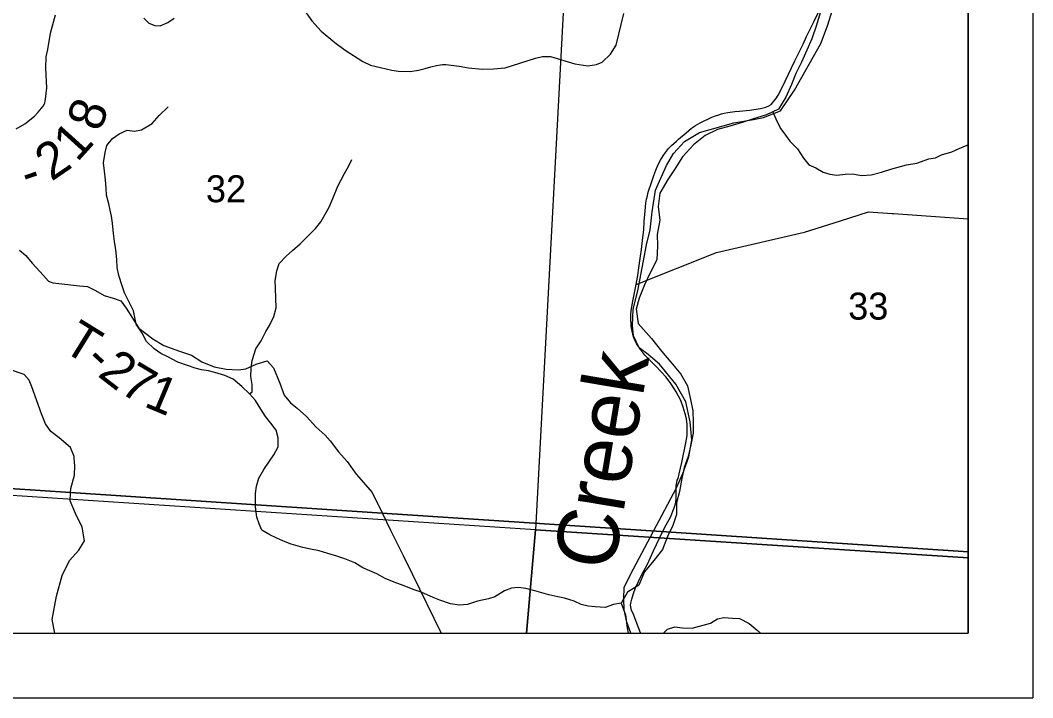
# Model space of a CAD drawing. Extents: x 0 to 34, y 0 to 22.
# Drawn here: x 7.429 to 9, y 14 to 15.051 of the extents above; entities that cross this region are included whole.
import ezdxf

# ---------------------------------------------------------------- set-up
doc = ezdxf.new("R2010")
doc.units = 0
for name, color, linetype in [('GM_X_County_Road', 7, 'Continuous'), ('GM_X_Minor_River', 7, 'Continuous'), ('GM_X_Minor_River_Text', 7, 'Continuous'), ('GM_X_Rail_Line', 7, 'Continuous'), ('GM_X_Section', 7, 'Continuous'), ('GM_X_Section_Text', 7, 'Continuous'), ('GM_X_Township_Road', 7, 'Continuous'), ('GM_X_Township_Road_Text', 7, 'Continuous'), ('GM_X_Unincorporated', 7, 'Continuous'), ('SH_Cut_Line', 7, 'Continuous'), ('SH_Data', 7, 'Continuous')]:
    doc.layers.add(name, color=color, linetype=linetype)

msp = doc.modelspace()

# ---------------------------------------------------------------- linework, layer by layer
at = {"layer": 'GM_X_County_Road'}
for points in [[(7.5131, 14.3715), (7.5129, 14.3744), (7.5073, 14.3881), (7.4899, 14.403), (7.4767, 14.4133), (7.4684, 14.4248), (7.4625, 14.4404), (7.4476, 14.4826), (7.4431, 14.4929), (7.4356, 14.5013), (7.4129, 14.5094)], [(7.4832, 14.1), (7.479, 14.1216), (7.4857, 14.1577), (7.4946, 14.1899), (7.5058, 14.213), (7.5206, 14.2292), (7.5291, 14.2432), (7.5254, 14.2645), (7.515, 14.2859), (7.5067, 14.3053), (7.5075, 14.3177), (7.508, 14.3246), (7.5138, 14.3451), (7.5139, 14.3599), (7.5135, 14.3657), (7.5131, 14.3715)]]:
    msp.add_lwpolyline(points, dxfattribs=at)
at = {"layer": 'GM_X_Minor_River'}
for points in [[(8.6705, 15.0627), (8.6644, 15.0437), (8.6571, 15.0221), (8.6495, 15.0049), (8.6412, 14.9859), (8.6324, 14.9688), (8.6256, 14.9513), (8.6168, 14.9316), (8.6058, 14.913), (8.5872, 14.9046), (8.5668, 14.8982), (8.5493, 14.8925), (8.53, 14.8868), (8.5111, 14.8819), (8.4917, 14.8724), (8.4739, 14.8579), (8.4568, 14.8393), (8.4451, 14.8214), (8.434, 14.8043), (8.4215, 14.7827), (8.4192, 14.7621), (8.4218, 14.7412), (8.4176, 14.7188), (8.4179, 14.7013), (8.4171, 14.6796), (8.4065, 14.6595), (8.3977, 14.6408), (8.3893, 14.6199), (8.3851, 14.6028), (8.3881, 14.5804), (8.4085, 14.5572), (8.424, 14.5378), (8.4387, 14.5206), (8.4542, 14.502), (8.4647, 14.4841), (8.4692, 14.4628), (8.4726, 14.4449), (8.4733, 14.4278), (8.4733, 14.4107), (8.4698, 14.3924), (8.4656, 14.3742), (8.4591, 14.3571), (8.4553, 14.3377), (8.4519, 14.3198), (8.4476, 14.3023), (8.4476, 14.2845), (8.4415, 14.267), (8.4335, 14.2499), (8.4259, 14.2301), (8.4122, 14.213), (8.3978, 14.1955), (8.3891, 14.1746), (8.3716, 14.1636), (8.3614, 14.1465), (8.3685, 14.1286), (8.3711, 14.1084), (8.3724, 14.1)], [(7.6068, 14.879), (7.6174, 14.8813), (7.6341, 14.8908), (7.645, 14.9033), (7.659, 14.9166)], [(8.5969, 14.9089), (8.6031, 14.8948), (8.6091, 14.8827), (8.6166, 14.8728), (8.6234, 14.8633), (8.6351, 14.8515), (8.6445, 14.837), (8.6525, 14.8267), (8.6634, 14.8222), (8.6748, 14.8157), (8.6853, 14.8122), (8.6959, 14.811), (8.7088, 14.8121), (8.7205, 14.8129), (8.7345, 14.8101), (8.7493, 14.8112), (8.7652, 14.8157), (8.78, 14.8202), (8.8042, 14.827), (8.8201, 14.8296), (8.8387, 14.8359), (8.8489, 14.8378), (8.8584, 14.8423), (8.8743, 14.8472), (8.886, 14.8521), (8.8985, 14.8574), (8.9, 14.8578)], [(8.3614, 14.1465), (8.3499, 14.1444), (8.3366, 14.1399), (8.3215, 14.141), (8.3105, 14.1421), (8.2996, 14.1448), (8.2886, 14.1497), (8.2735, 14.1546), (8.2633, 14.1565), (8.2493, 14.1599), (8.2387, 14.163), (8.2278, 14.166), (8.2138, 14.1694), (8.2017, 14.1709), (8.1915, 14.1701), (8.1805, 14.166), (8.1658, 14.1568), (8.1559, 14.1534), (8.1389, 14.1496), (8.1231, 14.1447), (8.1106, 14.1435), (8.0966, 14.1458), (8.0803, 14.1515), (8.0698, 14.1553), (8.0512, 14.164), (8.0388, 14.1681), (8.0248, 14.1734), (8.0093, 14.1795), (7.9957, 14.1848), (7.9824, 14.1924), (7.9609, 14.2018), (7.9484, 14.2094), (7.9329, 14.2155), (7.9205, 14.2196), (7.9065, 14.2238), (7.8932, 14.228), (7.8796, 14.2306), (7.8679, 14.2329), (7.8498, 14.2382), (7.8377, 14.2427), (7.8275, 14.2477), (7.8165, 14.2526), (7.8044, 14.2598), (7.7999, 14.2696), (7.7965, 14.2799), (7.7946, 14.2962), (7.7942, 14.3057), (7.7946, 14.317), (7.7961, 14.3284), (7.7995, 14.3406), (7.8071, 14.3542), (7.8162, 14.3671), (7.8226, 14.377), (7.8294, 14.3895), (7.8294, 14.4032), (7.8264, 14.4149), (7.8184, 14.4259), (7.8101, 14.4362), (7.8029, 14.4479), (7.7943, 14.4612), (7.7852, 14.4714), (7.7731, 14.4828), (7.7595, 14.4942), (7.747, 14.4998), (7.7315, 14.5044), (7.7213, 14.507), (7.7107, 14.5085), (7.7009, 14.5112), (7.6888, 14.5157), (7.6737, 14.5207), (7.6574, 14.5294), (7.6476, 14.5343), (7.637, 14.5415), (7.6253, 14.5529), (7.6185, 14.5654), (7.6094, 14.5794), (7.6053, 14.6003), (7.5977, 14.6147), (7.5913, 14.6283), (7.5875, 14.6389), (7.5826, 14.6553), (7.58, 14.6674), (7.5792, 14.6799), (7.5777, 14.6947), (7.5758, 14.708), (7.5743, 14.7205), (7.5724, 14.7364), (7.5709, 14.747), (7.569, 14.7565), (7.5671, 14.7664), (7.5634, 14.7796), (7.5626, 14.7903), (7.5618, 14.8035), (7.56, 14.8168), (7.5584, 14.8297), (7.5611, 14.846), (7.5637, 14.8566), (7.5728, 14.8676), (7.583, 14.8749), (7.5951, 14.8806), (7.6068, 14.879)], [(7.7852, 14.4714), (7.789, 14.4748), (7.789, 14.4858), (7.7871, 14.4984), (7.7875, 14.5116), (7.7894, 14.5234), (7.795, 14.5412), (7.803, 14.5537), (7.8102, 14.5682), (7.8162, 14.5776), (7.8226, 14.5913), (7.8264, 14.605), (7.826, 14.6201), (7.8253, 14.6357), (7.8249, 14.6474), (7.8276, 14.6626), (7.831, 14.6736), (7.8419, 14.685), (7.8518, 14.6941), (7.8639, 14.704), (7.8877, 14.7279), (7.8956, 14.7385), (7.902, 14.7495), (7.9085, 14.7613), (7.9141, 14.7746), (7.9221, 14.7935), (7.9274, 14.8034), (7.9323, 14.8133), (7.9387, 14.8243), (7.944, 14.8349)], [(8.427, 14.1), (8.4334, 14.1066), (8.4447, 14.11), (8.4565, 14.1085), (8.4716, 14.1081), (8.4833, 14.1108), (8.4999, 14.1157), (8.5109, 14.1222), (8.5207, 14.1245), (8.5343, 14.1237), (8.5453, 14.123), (8.56, 14.1154), (8.5725, 14.1048), (8.5779, 14.1)]]:
    msp.add_lwpolyline(points, dxfattribs=at)
at = {"layer": 'GM_X_Rail_Line'}
msp.add_lwpolyline([(8.3764, 14.1), (8.3704, 14.117), (8.3663, 14.1363), (8.3655, 14.1532), (8.3663, 14.171), (8.376, 14.1911), (8.4476, 14.3255), (8.4572, 14.348), (8.4665, 14.374), (8.471, 14.3998), (8.4685, 14.4281), (8.4619, 14.4593), (8.4466, 14.4864), (8.4208, 14.5178), (8.4108, 14.5265), (8.4033, 14.5326), (8.3897, 14.5428), (8.3808, 14.5613), (8.3793, 14.5778), (8.38, 14.6031), (8.3873, 14.6313), (8.4009, 14.7029), (8.4066, 14.7259), (8.4097, 14.7537), (8.4146, 14.7874), (8.4318, 14.8256), (8.4428, 14.8446), (8.4599, 14.8628), (8.4831, 14.877), (8.5363, 14.8921), (8.5668, 14.8972), (8.5825, 14.9002), (8.6085, 14.9106), (8.6302, 14.9428), (8.6712, 15.0152), (8.6817, 15.0426), (8.6979, 15.0941)], dxfattribs=at)
at = {"layer": 'GM_X_Section'}
msp.add_lwpolyline([(8.2829, 15.2756), (8.2289, 14.2604), (7.2187, 14.3265), (7.27, 15.3432)], close=True, dxfattribs=at)
at = {"layer": 'GM_X_Township_Road'}
for p, q in [((8.784, 14.7511), (8.9, 14.7429)), ((8.0372, 14.1923), (8.0826, 14.1))]:
    msp.add_line(p, q, dxfattribs=at)
for points in [[(7.8619, 15.0779), (7.882, 15.0501), (7.8962, 15.0344), (7.9174, 15.0169), (7.9337, 15.005), (7.9609, 14.987), (7.9727, 14.9813), (7.9882, 14.9776), (8.0059, 14.9736), (8.0163, 14.9723), (8.0344, 14.9719), (8.047, 14.9735), (8.0574, 14.9764), (8.0664, 14.9791), (8.0749, 14.9808), (8.0844, 14.9824), (8.0898, 14.9826), (8.1103, 14.9798), (8.125, 14.9772), (8.1459, 14.9753), (8.1635, 14.976), (8.1819, 14.9775), (8.2289, 14.9924), (8.2398, 14.9951), (8.252, 14.9949), (8.2897, 14.9835), (8.3098, 14.9805), (8.3231, 14.9827), (8.3321, 14.9859), (8.3448, 14.9984), (8.354, 15.0125), (8.3656, 15.0614)], [(8.4119, 14.2277), (8.4257, 14.2572), (8.4316, 14.2684), (8.4379, 14.2803), (8.444, 14.2945), (8.4456, 14.2995), (8.4464, 14.3031), (8.4468, 14.3084), (8.4468, 14.3171), (8.4468, 14.325), (8.4471, 14.3293), (8.4481, 14.3337), (8.4487, 14.3378), (8.4498, 14.3402), (8.4516, 14.3476), (8.4559, 14.3652), (8.4618, 14.3957), (8.4638, 14.4068), (8.464, 14.4153), (8.4638, 14.4241), (8.4628, 14.4328), (8.461, 14.4403), (8.4578, 14.4509), (8.454, 14.4612), (8.4471, 14.4745), (8.4445, 14.4787), (8.4384, 14.4878), (8.4315, 14.4972), (8.4237, 14.5055), (8.4149, 14.5149), (8.4074, 14.522), (8.4028, 14.5271), (8.3985, 14.5315), (8.3952, 14.5355), (8.3913, 14.5402), (8.3884, 14.5448), (8.3854, 14.5496), (8.3824, 14.5558), (8.3802, 14.5614), (8.3779, 14.5711), (8.3772, 14.5764), (8.3769, 14.5817), (8.3766, 14.5854), (8.3766, 14.5892), (8.3767, 14.5939), (8.3771, 14.6006), (8.3779, 14.6065), (8.3798, 14.6155), (8.3847, 14.641), (8.3872, 14.6552), (8.3886, 14.6634), (8.3916, 14.6849), (8.3931, 14.6956), (8.3953, 14.7141), (8.3965, 14.7258), (8.3975, 14.7391), (8.3986, 14.7553), (8.4, 14.7676), (8.401, 14.7737), (8.4022, 14.7787), (8.4031, 14.7824), (8.4041, 14.786), (8.4084, 14.7994), (8.4122, 14.8101), (8.4153, 14.8184), (8.419, 14.8274), (8.4228, 14.834), (8.4266, 14.8406), (8.4303, 14.8458), (8.4352, 14.852), (8.4397, 14.8569), (8.4472, 14.8638), (8.4505, 14.8664), (8.4623, 14.8766), (8.4705, 14.8835), (8.477, 14.888), (8.4842, 14.8922), (8.502, 14.9008), (8.508, 14.903), (8.513, 14.9046), (8.5173, 14.9059), (8.5213, 14.907), (8.5271, 14.9082), (8.5343, 14.9092), (8.5381, 14.9096), (8.5452, 14.9102), (8.5609, 14.9117), (8.5778, 14.914), (8.5858, 14.9161), (8.5904, 14.9184), (8.5942, 14.9207), (8.5982, 14.9254), (8.6015, 14.9293), (8.605, 14.9348), (8.6098, 14.9438), (8.6158, 14.9568), (8.631, 14.988), (8.6438, 15.0142), (8.6493, 15.0257), (8.661, 15.05), (8.6683, 15.0648)], [(7.4232, 14.8827), (7.4367, 14.8905), (7.4518, 14.9025), (7.4575, 14.9084), (7.4649, 14.9176), (7.4676, 14.9227), (7.4689, 14.9286), (7.4705, 14.9465), (7.4693, 14.9766), (7.4699, 14.9944), (7.4722, 15.0058), (7.4765, 15.031), (7.4842, 15.0595)], [(7.621, 15.0544), (7.6289, 15.0465), (7.6381, 15.0432), (7.6465, 15.0427), (7.6584, 15.0478), (7.6682, 15.0544)], [(8.3847, 14.641), (8.5094, 14.6907), (8.6461, 14.7223), (8.702, 14.7401), (8.745, 14.7539), (8.7821, 14.7512), (8.784, 14.7511)], [(7.4285, 14.6943), (7.4379, 14.6862), (7.4478, 14.6745), (7.4655, 14.655), (7.4733, 14.6465), (7.48, 14.6438), (7.4984, 14.6416), (7.5214, 14.6393), (7.5337, 14.6378), (7.5464, 14.6317), (7.5594, 14.624), (7.5736, 14.6198), (7.5855, 14.6156), (7.5939, 14.6044), (7.6132, 14.5735), (7.635, 14.5571), (7.652, 14.5463), (7.6763, 14.5378), (7.6952, 14.5313), (7.7114, 14.5213), (7.7303, 14.5136), (7.7489, 14.51), (7.7682, 14.5088), (7.7796, 14.5102), (7.7956, 14.5177), (7.8123, 14.5226), (7.8221, 14.5119), (7.8322, 14.4879), (7.8389, 14.4692), (7.8487, 14.4574), (7.8592, 14.4494), (7.8736, 14.4364), (7.8883, 14.4199), (7.9022, 14.4073), (7.9101, 14.3985), (7.9233, 14.3814), (7.9365, 14.3665), (7.9507, 14.347), (7.9513, 14.3463), (7.9752, 14.3184), (7.9912, 14.2858), (8.0038, 14.2602), (8.0233, 14.2207), (8.0372, 14.1923)], [(8.3917, 14.1), (8.3915, 14.1005), (8.3864, 14.1143), (8.381, 14.1279), (8.3777, 14.1358), (8.3766, 14.1409), (8.3763, 14.1437), (8.3768, 14.1468), (8.3779, 14.1527), (8.3805, 14.1617), (8.3838, 14.1706), (8.393, 14.1903), (8.4022, 14.2071), (8.4119, 14.2277)]]:
    msp.add_lwpolyline(points, dxfattribs=at)
at = {"layer": 'GM_X_Township_Road_Text'}
for points in [[(8.9, 14.2172), (8.9, 15.2383), (8.2829, 15.2756), (8.2289, 14.2604)], [(7.2077, 14.1), (8.2148, 14.1), (8.2289, 14.2604), (7.2187, 14.3265)], [(8.2148, 14.1), (8.9, 14.1), (8.9, 14.2172), (8.2289, 14.2604)]]:
    msp.add_lwpolyline(points, close=True, dxfattribs=at)
at = {"layer": 'GM_X_Unincorporated'}
msp.add_lwpolyline([(4.0882, 16.6114), (4.2937, 16.1161), (4.4847, 15.685), (4.802, 14.9692), (4.3998, 14.7897), (4.2904, 14.7408), (3.8099, 14.5285), (4.1531, 14.503), (4.2897, 14.5063), (4.438, 14.498), (6.2131, 14.3976), (7.1526, 14.3412), (7.2248, 14.3369), (7.5073, 14.3182), (7.991, 14.2863), (8.4238, 14.2578), (8.9, 14.2264), (8.9, 20.3234)], dxfattribs=at)
msp.add_lwpolyline([(7.2132, 14.1), (8.9, 14.1), (8.9, 14.2264), (8.4238, 14.2578), (7.991, 14.2863), (7.5073, 14.3182), (7.2248, 14.3369)], close=True, dxfattribs=at)
at = {"layer": 'SH_Cut_Line'}
msp.add_lwpolyline([(4.0882, 16.6114), (4.2937, 16.1161), (4.4847, 15.685), (4.802, 14.9692), (4.3998, 14.7897), (4.2904, 14.7408), (3.8099, 14.5285), (2.9778, 14.1609), (2.8399, 14.1), (8.9, 14.1), (8.9, 20.9)], dxfattribs=at)
at = {"layer": 'SH_Data'}
for p, q in [((9, 21), (9, 14)), ((8.9, 20.9), (8.9, 14.1)), ((2.1, 14.1), (8.9, 14.1)), ((2, 14), (9, 14))]:
    msp.add_line(p, q, dxfattribs=at)

# ---------------------------------------------------------------- texts
at = {"layer": 'GM_X_Minor_River_Text'}
msp.add_text('Creek', height=0.0947, rotation=80.4921, dxfattribs=at).set_placement((8.3496, 14.1949))
at = {"layer": 'GM_X_Section_Text'}
for s, p in [('32', (7.7175, 14.7688)), ('33', (8.7137, 14.5867))]:
    msp.add_text(s, height=0.04186, rotation=0, dxfattribs=at).set_placement(p)
at = {"layer": 'GM_X_Township_Road_Text'}
for s, rotation, p in [('8', 70.5365, (7.5536, 14.8766)), ('1', 47.9064, (7.5177, 14.8298)), ('2', 34.4311, (7.4779, 14.8004)), ('-', 18.9527, (7.4409, 14.7854)), ('T', 328.2667, (7.4926, 14.5402)), ('-', 317.1587, (7.5264, 14.5196)), ('2', 322.4255, (7.5479, 14.5)), ('7', 329.2123, (7.5817, 14.4746)), ('1', 337.3284, (7.6196, 14.4527))]:
    msp.add_text(s, height=0.0568, rotation=rotation, dxfattribs=at).set_placement(p)

doc.saveas('drawing.dxf')
